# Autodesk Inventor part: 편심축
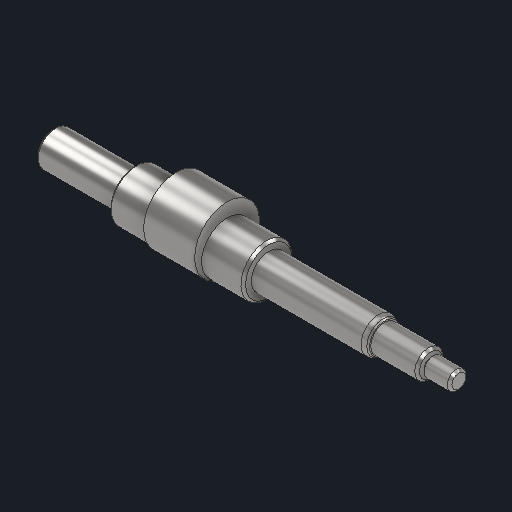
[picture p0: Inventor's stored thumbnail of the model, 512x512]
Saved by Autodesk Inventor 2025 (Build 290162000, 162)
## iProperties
Created: 2025-08
Part Number: 편심축
Material: 강철, 연강
Document SubType Name: Modeling
Designer: infra15
Density: 7.86 g/cm^3
Appearance: 기본값
Author: jhkim
Sending System: Autodesk Inventor 2026
Preprocessor: ST-DEVELOPER v20.1
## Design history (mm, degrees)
feature "솔리드1"
node "솔리드2"
